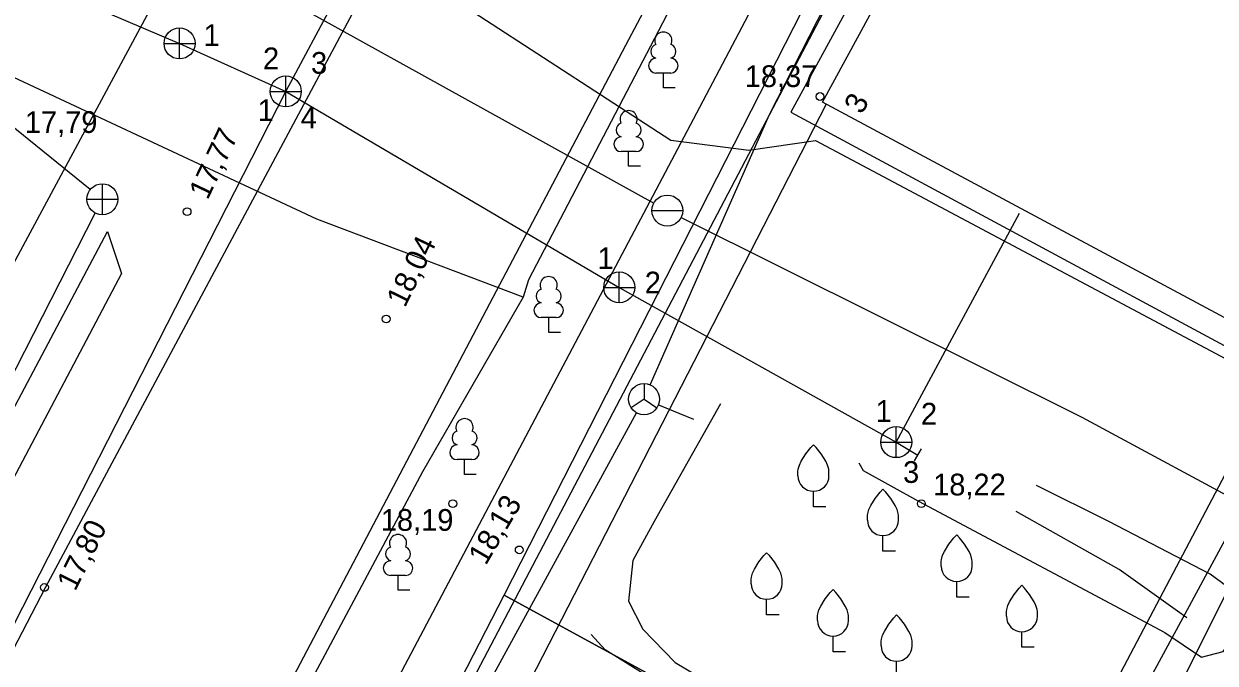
# Model space of a CAD drawing. Extents: x 713540 to 713867, y 6589774 to 6590061.
# Drawn here: x 713737.83 to 713776.25, y 6589948.37 to 6589968.97 of the extents above; entities that cross this region are included whole.
import ezdxf

# ---------------------------------------------------------------- set-up
doc = ezdxf.new("R2010")
doc.units = 0
for name, color, linetype in [('AED', 7, 'Continuous'), ('HALJASTUS', 7, 'Continuous'), ('HOONE', 7, 'Continuous'), ('HOONEDET', 7, 'Continuous'), ('KKAEV', 7, 'Continuous'), ('KORGUS', 7, 'Continuous'), ('KTRASS', 7, 'Continuous'), ('MPKAABEL', 7, 'Continuous'), ('PUU', 7, 'Continuous'), ('SIKAEV', 7, 'Continuous'), ('SITRASS', 7, 'Continuous'), ('SKTRASS', 7, 'Continuous'), ('TEE', 7, 'Continuous'), ('TORU NR', 7, 'Continuous'), ('VKAEV', 7, 'Continuous'), ('VTRASS', 7, 'Continuous'), ('Слой 1', 7, 'Continuous')]:
    doc.layers.add(name, color=color, linetype=linetype)

msp = doc.modelspace()

# ---------------------------------------------------------------- linework, layer by layer
at = {"layer": 'AED'}
msp.add_lwpolyline([(713763.714, 6589966.383), (713748.668, 6589937.119)], dxfattribs=at)
at = {"layer": 'HALJASTUS'}
for points in [[(713760.304, 6589956.722), (713758.16, 6589952.94), (713757.47, 6589951.68), (713757.33, 6589950.37), (713757.8, 6589949.47), (713758.84, 6589948.39), (713761.14, 6589947.03), (713764.66, 6589945.48), (713769.93, 6589943.18), (713772.72, 6589941.66), (713777.94, 6589938.37), (713784.38, 6589934.37), (713785.89, 6589933.2), (713785.84, 6589932.59), (713785.7, 6589931.83)], [(713764.759, 6589954.826), (713764.9, 6589954.58), (713766.69, 6589953.59), (713774.63, 6589949.36), (713775.81, 6589948.56), (713776.51, 6589948.75), (713776.98, 6589949.41), (713777.22, 6589950.16), (713776.98, 6589950.58), (713776.09, 6589951.24), (713772.82, 6589952.93), (713770.49, 6589954.091)], [(713775.34, 6589949.83), (713773.16, 6589951.39), (713769.833, 6589953.255)], [(713784.59, 6589933.17), (713781.02, 6589935.33), (713772.33, 6589940.41), (713769.84, 6589941.82), (713765.68, 6589943.71), (713762.99, 6589944.84), (713760.91, 6589946.1), (713756.58, 6589948.8), (713756.13, 6589949.298)]]:
    msp.add_lwpolyline(points, dxfattribs=at)
at = {"layer": 'HOONE'}
for points in [[(713729.99, 6589999.65), (713726.52, 6589993), (713721.37, 6589983.38), (713731.962, 6589977.615), (713740.57, 6589972.93), (713758.149, 6589963.196)], [(713778.047, 6589958.699), (713763.592, 6589966.452), (713774.345, 6589986.196), (713788.658, 6589978.195), (713778.047, 6589958.699)], [(713759.032, 6589962.726), (713771.957, 6589956.298), (713777.85, 6589953.12)], [(713760.52, 6589918.72), (713762.58, 6589922.57), (713777.85, 6589953.12)]]:
    msp.add_lwpolyline(points, dxfattribs=at)
at = {"layer": 'HOONEDET'}
msp.add_lwpolyline([(713783.5, 6589969.08), (713785.14, 6589968.31), (713790.12, 6589978.299), (713774.007, 6589987.074), (713762.57, 6589966.126), (713778.365, 6589957.631), (713782.52, 6589965.05), (713783.84, 6589967.18)], dxfattribs=at)
at = {"layer": 'KKAEV'}
for p, q in [((713742.856, 6589967.841), (713742.856, 6589968.841)), ((713742.356, 6589968.341), (713743.356, 6589968.341)), ((713746.283, 6589966.293), (713746.283, 6589967.293)), ((713745.783, 6589966.793), (713746.783, 6589966.793)), ((713740.367, 6589962.819), (713740.367, 6589963.819)), ((713739.867, 6589963.319), (713740.867, 6589963.319)), ((713757.037, 6589959.98), (713757.037, 6589960.98)), ((713756.537, 6589960.48), (713757.537, 6589960.48)), ((713765.967, 6589954.992), (713765.967, 6589955.992)), ((713765.467, 6589955.492), (713766.467, 6589955.492))]:
    msp.add_line(p, q, dxfattribs=at)
for centre in [(713742.856, 6589968.341), (713746.283, 6589966.793), (713740.367, 6589963.319), (713757.037, 6589960.48), (713765.967, 6589955.492)]:
    msp.add_circle(centre, 0.5, dxfattribs=at)
at = {"layer": 'KORGUS'}
for centre in [(713763.51, 6589966.63), (713743.1, 6589962.92), (713749.52, 6589959.46), (713751.67, 6589953.51), (713766.78, 6589953.51), (713753.81, 6589952.02), (713738.5, 6589950.81)]:
    msp.add_circle(centre, 0.125, dxfattribs=at)
at = {"layer": 'KTRASS'}
for p, q in [((713746.283, 6589966.793), (713760.755, 6589993.794)), ((713723.237, 6589976.699), (713742.856, 6589968.341)), ((713742.856, 6589968.341), (713746.283, 6589966.793)), ((713728.183, 6589931.342), (713746.283, 6589966.793)), ((713746.283, 6589966.793), (713757.037, 6589960.48)), ((713765.967, 6589955.492), (713769.945, 6589962.866)), ((713757.037, 6589960.48), (713765.967, 6589955.492)), ((713765.967, 6589955.492), (713766.66, 6589955.072)), ((713766.556, 6589954.894), (713766.783, 6589955.281))]:
    msp.add_line(p, q, dxfattribs=at)
at = {"layer": 'MPKAABEL'}
for points in [[(713796.776, 6590060.636), (713793.419, 6590054.295), (713774.719, 6590018.872), (713756.007, 6589983.478), (713738.52, 6589950.8), (713723.469, 6589921.84)], [(713732.905, 6589979.347), (713738.612, 6589976.697), (713744.311, 6589973.432), (713750.492, 6589970.566), (713758.7, 6589965.226), (713761.213, 6589964.896), (713763.366, 6589965.211), (713774.093, 6589959.513), (713777.1, 6589957.91), (713777.68, 6589957.38), (713777.72, 6589957.03), (713777.72, 6589956.58), (713777.41, 6589956.05), (713772.78, 6589947.26), (713769.66, 6589941.85), (713766.66, 6589937.29), (713759.1, 6589926.34), (713753.63, 6589918.22)]]:
    msp.add_lwpolyline(points, dxfattribs=at)
at = {"layer": 'PUU'}
for p, q in [((713758.698, 6589967.386), (713758.218, 6589967.386)), ((713758.458, 6589966.911), (713758.458, 6589967.386)), ((713758.838, 6589966.911), (713758.458, 6589966.911)), ((713757.578, 6589964.855), (713757.098, 6589964.855)), ((713757.338, 6589964.38), (713757.338, 6589964.855)), ((713757.718, 6589964.38), (713757.338, 6589964.38)), ((713755, 6589959.505), (713754.52, 6589959.505)), ((713754.76, 6589959.03), (713754.76, 6589959.505)), ((713755.14, 6589959.03), (713754.76, 6589959.03)), ((713752.286, 6589954.929), (713751.806, 6589954.929)), ((713752.046, 6589954.454), (713752.046, 6589954.929)), ((713752.426, 6589954.454), (713752.046, 6589954.454)), ((713763.3, 6589953.41), (713763.3, 6589953.91)), ((713763.7, 6589953.41), (713763.3, 6589953.41)), ((713765.54, 6589951.98), (713765.54, 6589952.48)), ((713765.94, 6589951.98), (713765.54, 6589951.98)), ((713750.143, 6589951.193), (713749.663, 6589951.193)), ((713749.903, 6589950.718), (713749.903, 6589951.193)), ((713767.92, 6589950.5), (713767.92, 6589951)), ((713750.283, 6589950.718), (713749.903, 6589950.718)), ((713761.79, 6589949.93), (713761.79, 6589950.43)), ((713768.32, 6589950.5), (713767.92, 6589950.5)), ((713762.19, 6589949.93), (713761.79, 6589949.93)), ((713770.02, 6589948.88), (713770.02, 6589949.38)), ((713763.93, 6589948.74), (713763.93, 6589949.24)), ((713764.33, 6589948.74), (713763.93, 6589948.74)), ((713770.42, 6589948.88), (713770.02, 6589948.88)), ((713765.98, 6589947.93), (713765.98, 6589948.43))]:
    msp.add_line(p, q, dxfattribs=at)
for points in [[(713762.8, 6589954.41), (713762.8, 6589954.56), (713762.81, 6589954.625), (713762.845, 6589954.755), (713762.905, 6589954.875), (713763.05, 6589955.11), (713763.21, 6589955.315), (713763.3, 6589955.41)], [(713763.8, 6589954.41), (713763.8, 6589954.56), (713763.79, 6589954.625), (713763.755, 6589954.755), (713763.695, 6589954.875), (713763.55, 6589955.11), (713763.39, 6589955.315), (713763.3, 6589955.41)], [(713765.04, 6589952.98), (713765.04, 6589953.13), (713765.05, 6589953.195), (713765.085, 6589953.325), (713765.145, 6589953.445), (713765.29, 6589953.68), (713765.45, 6589953.885), (713765.54, 6589953.98)], [(713766.04, 6589952.98), (713766.04, 6589953.13), (713766.03, 6589953.195), (713765.995, 6589953.325), (713765.935, 6589953.445), (713765.79, 6589953.68), (713765.63, 6589953.885), (713765.54, 6589953.98)], [(713767.42, 6589951.5), (713767.42, 6589951.65), (713767.43, 6589951.715), (713767.465, 6589951.845), (713767.525, 6589951.965), (713767.67, 6589952.2), (713767.83, 6589952.405), (713767.92, 6589952.5)], [(713768.42, 6589951.5), (713768.42, 6589951.65), (713768.41, 6589951.715), (713768.375, 6589951.845), (713768.315, 6589951.965), (713768.17, 6589952.2), (713768.01, 6589952.405), (713767.92, 6589952.5)], [(713761.29, 6589950.93), (713761.29, 6589951.08), (713761.3, 6589951.145), (713761.335, 6589951.275), (713761.395, 6589951.395), (713761.54, 6589951.63), (713761.7, 6589951.835), (713761.79, 6589951.93)], [(713762.29, 6589950.93), (713762.29, 6589951.08), (713762.28, 6589951.145), (713762.245, 6589951.275), (713762.185, 6589951.395), (713762.04, 6589951.63), (713761.88, 6589951.835), (713761.79, 6589951.93)], [(713763.43, 6589949.74), (713763.43, 6589949.89), (713763.44, 6589949.955), (713763.475, 6589950.085), (713763.535, 6589950.205), (713763.68, 6589950.44), (713763.84, 6589950.645), (713763.93, 6589950.74)], [(713764.43, 6589949.74), (713764.43, 6589949.89), (713764.42, 6589949.955), (713764.385, 6589950.085), (713764.325, 6589950.205), (713764.18, 6589950.44), (713764.02, 6589950.645), (713763.93, 6589950.74)], [(713769.52, 6589949.88), (713769.52, 6589950.03), (713769.53, 6589950.095), (713769.565, 6589950.225), (713769.625, 6589950.345), (713769.77, 6589950.58), (713769.93, 6589950.785), (713770.02, 6589950.88)], [(713770.52, 6589949.88), (713770.52, 6589950.03), (713770.51, 6589950.095), (713770.475, 6589950.225), (713770.415, 6589950.345), (713770.27, 6589950.58), (713770.11, 6589950.785), (713770.02, 6589950.88)], [(713765.48, 6589948.93), (713765.48, 6589949.08), (713765.49, 6589949.145), (713765.525, 6589949.275), (713765.585, 6589949.395), (713765.73, 6589949.63), (713765.89, 6589949.835), (713765.98, 6589949.93)], [(713766.48, 6589948.93), (713766.48, 6589949.08), (713766.47, 6589949.145), (713766.435, 6589949.275), (713766.375, 6589949.395), (713766.23, 6589949.63), (713766.07, 6589949.835), (713765.98, 6589949.93)]]:
    msp.add_lwpolyline(points, dxfattribs=at)
for centre, radius, start, end in [((713758.458, 6589968.431), 0.277, 332.5799, 207.4201), ((713758.288, 6589968.083), 0.233, 109.0217, 253.1415), ((713758.629, 6589968.083), 0.233, 286.8508, 70.9859), ((713758.221, 6589967.623), 0.238, 90.0016, 269.3953), ((713758.696, 6589967.623), 0.238, 270.6047, 89.9984), ((713757.338, 6589965.9), 0.277, 332.5799, 207.4201), ((713757.168, 6589965.552), 0.233, 109.0217, 253.1415), ((713757.509, 6589965.552), 0.233, 286.8508, 70.9859), ((713757.101, 6589965.092), 0.238, 90.0016, 269.3953), ((713757.576, 6589965.092), 0.238, 270.6047, 89.9984), ((713754.76, 6589960.55), 0.277, 332.5799, 207.4201), ((713754.59, 6589960.202), 0.233, 109.0217, 253.1415), ((713754.93, 6589960.202), 0.233, 286.8508, 70.9859), ((713754.522, 6589959.742), 0.238, 90.0016, 269.3953), ((713754.997, 6589959.742), 0.238, 270.6047, 89.9984), ((713752.046, 6589955.974), 0.277, 332.5799, 207.4201), ((713751.876, 6589955.626), 0.233, 109.0217, 253.1415), ((713752.216, 6589955.626), 0.233, 286.8508, 70.9859), ((713751.808, 6589955.166), 0.238, 90.0016, 269.3953), ((713752.283, 6589955.166), 0.238, 270.6047, 89.9984), ((713763.3, 6589954.41), 0.5, 180, 0), ((713765.54, 6589952.98), 0.5, 180, 0), ((713749.903, 6589952.238), 0.277, 332.5799, 207.4201), ((713749.733, 6589951.891), 0.233, 109.0217, 253.1415), ((713750.073, 6589951.891), 0.233, 286.8508, 70.9859), ((713749.666, 6589951.431), 0.238, 90.0016, 269.3953), ((713750.141, 6589951.431), 0.238, 270.6047, 89.9984), ((713767.92, 6589951.5), 0.5, 180, 0), ((713761.79, 6589950.93), 0.5, 180, 0), ((713770.02, 6589949.88), 0.5, 180, 0), ((713763.93, 6589949.74), 0.5, 180, 0), ((713765.98, 6589948.93), 0.5, 180, 0)]:
    msp.add_arc(centre, radius, start, end, dxfattribs=at)
at = {"layer": 'SIKAEV'}
for p, q in [((713757.835, 6589957.377), (713757.835, 6589956.877)), ((713757.835, 6589956.877), (713757.42, 6589956.602)), ((713757.835, 6589956.877), (713758.25, 6589956.602))]:
    msp.add_line(p, q, dxfattribs=at)
msp.add_circle((713757.835, 6589956.877), 0.5, dxfattribs=at)
at = {"layer": 'SITRASS'}
for points in [[(713758.037, 6589957.335), (713761.879, 6589966.052), (713768.07, 6589978.18), (713774.37, 6589989.97), (713787.88, 6590015.87), (713811.74, 6590060.636)], [(713784.17, 6589966.48), (713783.15, 6589964.52), (713775.28, 6589949.95), (713771.6, 6589943.17), (713766.77, 6589935.04), (713757.84, 6589920.53)], [(713758.299, 6589956.691), (713759.435, 6589956.236)], [(713733.955, 6589912.506), (713745.74, 6589934.74), (713757.595, 6589956.438)]]:
    msp.add_lwpolyline(points, dxfattribs=at)
at = {"layer": 'SKTRASS'}
for points in [[(713739.978, 6589963.633), (713737.147, 6589965.918)], [(713725.683, 6589934.563), (713740.14, 6589962.874)]]:
    msp.add_lwpolyline(points, dxfattribs=at)
at = {"layer": 'TEE'}
for points in [[(713745.323, 6589939.226), (713759.427, 6589965.904), (713771.434, 6589988.676), (713771.387, 6589989.539)], [(713743.761, 6589942.675), (713757.248, 6589968.279), (713767.715, 6589988.031), (713768.327, 6589988.929)], [(713773.399, 6589987.91), (713761.879, 6589966.052), (713747.389, 6589938.479), (713748.668, 6589937.119), (713747.341, 6589934.622), (713748.274, 6589934.123), (713758.415, 6589927.701), (713757.661, 6589926.588), (713764.712, 6589921.738), (713761.12, 6589915.04)], [(713725.114, 6589931.055), (713724.723, 6589932.457), (713733.058, 6589948.204), (713740.528, 6589962.284), (713740.986, 6589960.924), (713733.856, 6589947.446), (713725.114, 6589931.055)]]:
    msp.add_lwpolyline(points, dxfattribs=at)
at = {"layer": 'VKAEV'}
msp.add_line((713758.086, 6589962.953), (713759.086, 6589962.953), dxfattribs=at)
msp.add_circle((713758.586, 6589962.953), 0.5, dxfattribs=at)
at = {"layer": 'VTRASS'}
for points in [[(713786.9, 6590022.053), (713786.663, 6590021.42), (713779.918, 6590009.263), (713774.768, 6590000.13), (713772.089, 6589995.293), (713771.2, 6589993.262), (713769.595, 6589990.576), (713766.999, 6589985.749), (713760.969, 6589973.854), (713754.105, 6589960.72), (713753.933, 6589960.165), (713750.695, 6589954.533), (713746.011, 6589945.782), (713740.356, 6589934.918), (713733.16, 6589921.546), (713727.052, 6589912.116), (713721.352, 6589902.724), (713721.093, 6589902.329)], [(713753.933, 6589960.165), (713747.285, 6589962.672), (713735.18, 6589968.324), (713730.512, 6589969.691)]]:
    msp.add_lwpolyline(points, dxfattribs=at)
at = {"layer": 'Слой 1'}
for points in [[(713800.41, 6589978.59), (713796.9, 6589972.02), (713811.25, 6589964.46), (713800.51, 6589942.86), (713790.89, 6589929.51), (713786.76, 6589932.33), (713753.32, 6589950.56), (713774.49, 6589992.04)], [(713689.74, 6589981), (713702.78, 6589983.59), (713701.84, 6589988.96), (713713.13, 6589989.8), (713713.92, 6589985.29), (713742.5, 6589970.55), (713718.97, 6589926.81), (713697.63, 6589938.02)], [(713753.32, 6589950.56), (713786.76, 6589932.33), (713765.63, 6589894.55), (713732.87, 6589910.81)]]:
    msp.add_lwpolyline(points, close=True, dxfattribs=at)

# ---------------------------------------------------------------- texts
at = {"layer": 'HOONE'}
msp.add_text('3', height=0.7, rotation=61.6102, dxfattribs=at).set_placement((713764.864, 6589966.026))
at = {"layer": 'KORGUS'}
for s, p in [('18,37', (713761.083, 6589966.935)), ('17,79', (713737.866, 6589965.455)), ('18,22', (713767.158, 6589953.775)), ('18,19', (713749.346, 6589952.635))]:
    msp.add_text(s, height=0.7, dxfattribs=at).set_placement(p)
for s, rotation, p in [('17,77', 64.5123, (713743.761, 6589963.272)), ('18,04', 64.0268, (713750.125, 6589959.802)), ('18,13', 59.7499, (713752.733, 6589951.495)), ('17,80', 63.5804, (713739.491, 6589950.66))]:
    msp.add_text(s, height=0.7, rotation=rotation, dxfattribs=at).set_placement(p)
at = {"layer": 'TORU NR'}
for s, p in [('1', (713743.631, 6589968.259)), ('2', (713745.548, 6589967.509)), ('3', (713747.096, 6589967.362)), ('1', (713745.376, 6589965.838)), ('4', (713746.764, 6589965.605)), ('1', (713756.335, 6589961.071)), ('2', (713757.858, 6589960.285)), ('1', (713765.304, 6589956.145)), ('2', (713766.766, 6589956.059)), ('3', (713766.188, 6589954.179))]:
    msp.add_text(s, height=0.7, dxfattribs=at).set_placement(p)

doc.saveas('drawing.dxf')
